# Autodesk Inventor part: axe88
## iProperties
Shininess: 21.0
Length Units: 11269
Angle Units: 11279
Time Units: 11290
Mass Units: 11283
Length Display Precision: 3
Angle Display Precision: 2
Compacted: True
Created: 2001-12
Part Number: axe88
Material: Par défaut
Document SubType Name: Modélisation
Designer: pichon
Density: 0.0
Volumn: 0.0
Area: 0.0
PropertySet Name: Model Information
Control State: 0
Master: False
Checked Out: False
Author: pichon
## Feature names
1. Révolution1 [Revolution]
